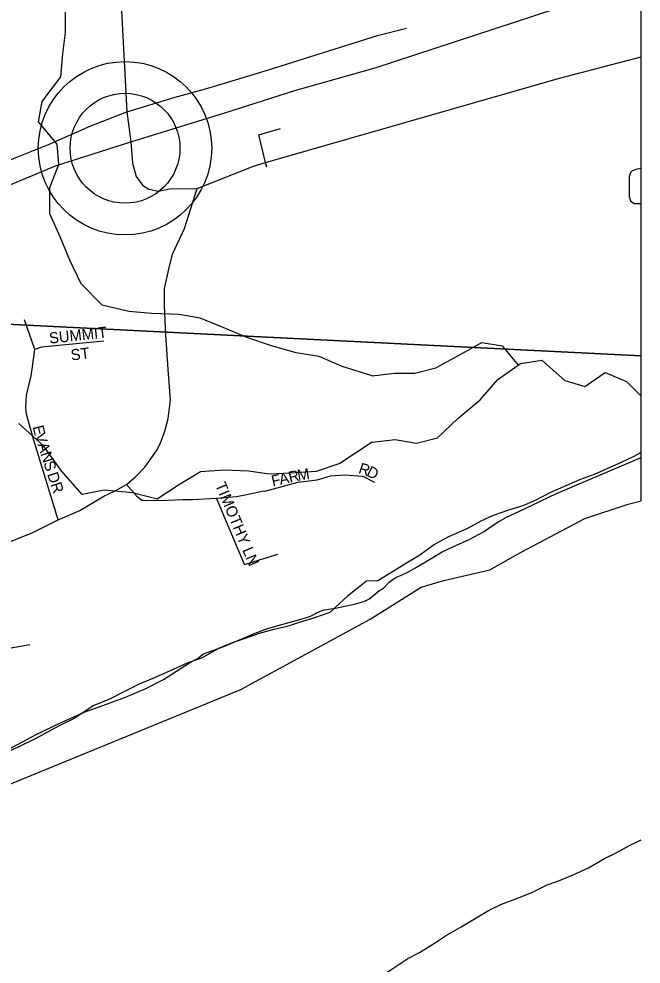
# Model space of a CAD drawing. Extents: x 1949938.81 to 1949945.61, y 152207.65 to 152214.09.
# Drawn here: x 1949945.073 to 1949945.607, y 152208.429 to 152209.24 of the extents above; entities that cross this region are included whole.
import ezdxf

# ---------------------------------------------------------------- set-up
doc = ezdxf.new("R2010")
doc.units = 0
for name, color, linetype in [('GM_X_Airport_Class_3', 7, 'Continuous'), ('GM_X_County', 7, 'Continuous'), ('GM_X_County_Road', 7, 'Continuous'), ('GM_X_Major_River', 7, 'Continuous'), ('GM_X_Minor_River', 7, 'Continuous'), ('GM_X_Section', 7, 'Continuous'), ('GM_X_Township', 7, 'Continuous'), ('GM_X_Township_ROW', 7, 'Continuous'), ('GM_X_Township_Subdivision', 7, 'Continuous'), ('GM_X_Township_Subdivision_Text', 7, 'Continuous'), ('GM_X_Unincorporated', 7, 'Continuous'), ('GM_X_Unincorporated_Location', 7, 'Continuous'), ('GM_X_US_Route', 7, 'Continuous')]:
    doc.layers.add(name, color=color, linetype=linetype)

msp = doc.modelspace()

# ---------------------------------------------------------------- linework, layer by layer
at = {"layer": 'GM_X_Airport_Class_3'}
msp.add_line((1949945.60686, 152209.0816), (1949945.60686, 152209.11163), dxfattribs=at)
msp.add_lwpolyline([(1949945.60686, 152209.11163), (1949945.6022, 152209.11103), (1949945.59893, 152209.10959), (1949945.59774, 152209.10824), (1949945.59671, 152209.10482), (1949945.59667, 152209.08762), (1949945.59786, 152209.08393), (1949945.60099, 152209.08163), (1949945.60686, 152209.0816)], dxfattribs=at)
at = {"layer": 'GM_X_County'}
for points in [[(1949945.60686, 152208.82659), (1949945.60686, 152214.0874), (1949938.80686, 152214.0874), (1949938.80686, 152213.18128)], [(1949942.51034, 152208.01072), (1949942.8268, 152208.00464), (1949942.9926, 152208.00728), (1949943.04181, 152208.01904), (1949943.19019, 152208.0433), (1949943.32418, 152208.05808), (1949943.55507, 152208.10092), (1949944.00133, 152208.20671), (1949944.06493, 152208.23174), (1949944.52367, 152208.38458), (1949944.91164, 152208.52796), (1949945.03125, 152208.56968), (1949945.26327, 152208.66452), (1949945.37438, 152208.72503), (1949945.41796, 152208.75242), (1949945.43768, 152208.75815), (1949945.47712, 152208.76732), (1949945.50403, 152208.78255), (1949945.55862, 152208.81147), (1949945.59578, 152208.82368), (1949945.60686, 152208.82659)]]:
    msp.add_lwpolyline(points, dxfattribs=at)
at = {"layer": 'GM_X_County_Road'}
for points in [[(1949945.16079, 152209.24715), (1949945.16547, 152209.16044), (1949945.16887, 152209.13464)], [(1949945.22775, 152209.17881), (1949945.23695, 152209.18138), (1949945.28721, 152209.19655), (1949945.3807, 152209.22584), (1949945.40543, 152209.23219)], [(1949945.22586, 152209.09445), (1949945.27406, 152209.11376), (1949945.28463, 152209.1168), (1949945.53684, 152209.18937), (1949945.60686, 152209.20755)], [(1949945.16547, 152209.16044), (1949945.20692, 152209.17299), (1949945.22775, 152209.17881)], [(1949944.7487, 152208.97684), (1949944.78583, 152208.98937), (1949944.8436, 152209.01822), (1949944.91631, 152209.05182), (1949944.97891, 152209.07991), (1949944.99822, 152209.09001), (1949945.04072, 152209.1094), (1949945.09823, 152209.13241), (1949945.1345, 152209.14834), (1949945.16547, 152209.16044)], [(1949945.16887, 152209.13464), (1949945.16887, 152209.13464), (1949945.17041, 152209.11644), (1949945.17338, 152209.1048), (1949945.17905, 152209.0975), (1949945.18447, 152209.09397), (1949945.19258, 152209.09235), (1949945.20205, 152209.09425), (1949945.22586, 152209.09445)], [(1949945.08816, 152208.80113), (1949945.10645, 152208.81028), (1949945.12509, 152208.81813), (1949945.14569, 152208.83064), (1949945.1555, 152208.83506), (1949945.16532, 152208.84046), (1949945.17317, 152208.84757), (1949945.18102, 152208.85542), (1949945.19083, 152208.86941), (1949945.19402, 152208.87554), (1949945.19819, 152208.88634), (1949945.20087, 152208.89711), (1949945.20292, 152208.91315), (1949945.20109, 152208.93913), (1949945.19892, 152208.96917), (1949945.1977, 152208.99372), (1949945.19794, 152209.00887), (1949945.2015, 152209.02539), (1949945.20474, 152209.03835), (1949945.2151, 152209.06038), (1949945.22586, 152209.09445)], [(1949944.41994, 152208.55828), (1949944.44868, 152208.57015), (1949944.49406, 152208.58988), (1949944.52449, 152208.60195), (1949944.57656, 152208.61961), (1949944.63875, 152208.63945), (1949944.64745, 152208.64222), (1949944.69231, 152208.65199), (1949944.74952, 152208.67284), (1949944.8104, 152208.69434), (1949944.85513, 152208.70878), (1949944.86482, 152208.7105), (1949944.89699, 152208.72448), (1949944.94572, 152208.7428), (1949944.98591, 152208.76004), (1949945.041, 152208.78201), (1949945.08486, 152208.79948), (1949945.08816, 152208.80113)]]:
    msp.add_lwpolyline(points, dxfattribs=at)
at = {"layer": 'GM_X_Major_River'}
for points in [[(1949945.60686, 152208.86793), (1949945.60018, 152208.86435), (1949945.59036, 152208.85977), (1949945.56654, 152208.84909), (1949945.55406, 152208.84451), (1949945.54234, 152208.83955), (1949945.52911, 152208.83383), (1949945.51588, 152208.82696), (1949945.50529, 152208.82239), (1949945.49395, 152208.81894), (1949945.47996, 152208.81398), (1949945.46937, 152208.80902), (1949945.45728, 152208.80254), (1949945.44102, 152208.7953), (1949945.42968, 152208.7892), (1949945.41608, 152208.7793), (1949945.40626, 152208.77359), (1949945.39492, 152208.76636), (1949945.38094, 152208.75798), (1949945.3711, 152208.75757)], [(1949945.3711, 152208.75757), (1949945.35475, 152208.74461), (1949945.34791, 152208.73854), (1949945.33971, 152208.73064), (1949945.32648, 152208.72609), (1949945.31627, 152208.72306), (1949945.30189, 152208.71851), (1949945.29055, 152208.71586), (1949945.2792, 152208.71283), (1949945.2671, 152208.70828), (1949945.25689, 152208.70487), (1949945.24517, 152208.70032), (1949945.22966, 152208.6916), (1949945.21794, 152208.68743), (1949945.20205, 152208.68023), (1949945.18768, 152208.67416), (1949945.17596, 152208.66924), (1949945.16348, 152208.66279), (1949945.15062, 152208.65635), (1949945.13663, 152208.65066), (1949945.12074, 152208.64005), (1949945.1075, 152208.6336), (1949945.08784, 152208.62299), (1949945.07346, 152208.61579), (1949945.05758, 152208.60859)], [(1949945.37365, 152208.41241), (1949945.3913, 152208.42363), (1949945.40679, 152208.43391), (1949945.41662, 152208.43886), (1949945.42871, 152208.44647), (1949945.43891, 152208.45332), (1949945.45252, 152208.46094), (1949945.46537, 152208.46856), (1949945.47594, 152208.47503), (1949945.48691, 152208.48037), (1949945.49939, 152208.48495), (1949945.513, 152208.49029), (1949945.52623, 152208.49715), (1949945.53682, 152208.50059), (1949945.54854, 152208.50555), (1949945.56177, 152208.51165), (1949945.57537, 152208.51965), (1949945.58558, 152208.52461), (1949945.59692, 152208.5307), (1949945.60686, 152208.53555)]]:
    msp.add_lwpolyline(points, dxfattribs=at)
at = {"layer": 'GM_X_Minor_River'}
for points in [[(1949945.37606, 152208.93377), (1949945.35022, 152208.94196), (1949945.33057, 152208.95038), (1949945.31089, 152208.9535), (1949945.28971, 152208.95965), (1949945.26929, 152208.96656), (1949945.24661, 152208.97575), (1949945.22846, 152208.98342), (1949945.2103, 152208.98652), (1949945.18683, 152208.98737), (1949945.16714, 152208.98896), (1949945.14444, 152208.99436), (1949945.12634, 152209.01265), (1949945.11658, 152209.03319), (1949945.10834, 152209.05297), (1949945.09933, 152209.07274), (1949945.09942, 152209.09552), (1949945.10708, 152209.11524), (1949945.10564, 152209.13272), (1949945.08981, 152209.15176), (1949945.09291, 152209.16922), (1949945.10891, 152209.19042), (1949945.1105, 152209.21017), (1949945.11285, 152209.22839), (1949945.11292, 152209.24586)], [(1949945.37606, 152208.93377), (1949945.39522, 152208.93603), (1949945.41263, 152208.93602), (1949945.4308, 152208.94056), (1949945.45277, 152208.95268), (1949945.4702, 152208.96254), (1949945.48761, 152208.95949), (1949945.50149, 152208.94292)], [(1949945.37605, 152208.87686), (1949945.39589, 152208.87913), (1949945.41405, 152208.87608), (1949945.43222, 152208.88062), (1949945.44966, 152208.8973), (1949945.46861, 152208.91322), (1949945.48378, 152208.93066), (1949945.50348, 152208.9443), (1949945.52165, 152208.94732), (1949945.54131, 152208.92986), (1949945.55871, 152208.92453), (1949945.57614, 152208.93666), (1949945.5943, 152208.92906), (1949945.60686, 152208.91644)], [(1949945.37605, 152208.87686), (1949945.34836, 152208.85845), (1949945.32788, 152208.85169), (1949945.30591, 152208.85025), (1949945.28773, 152208.84956), (1949945.27033, 152208.8519), (1949945.24912, 152208.85274), (1949945.22867, 152208.8513), (1949945.20969, 152208.83998), (1949945.19146, 152208.8279), (1949945.17028, 152208.83329), (1949945.14605, 152208.83566), (1949945.1271, 152208.83194), (1949945.10901, 152208.8525), (1949945.09396, 152208.87382), (1949945.07283, 152208.89288)]]:
    msp.add_lwpolyline(points, dxfattribs=at)
at = {"layer": 'GM_X_Section'}
for p, q in [((1949945.60686, 152208.95108), (1949945.60686, 152209.95427)), ((1949945.60686, 152208.86374), (1949945.60686, 152208.95108))]:
    msp.add_line(p, q, dxfattribs=at)
for points in [[(1949945.60686, 152209.95427), (1949944.65667, 152210.00648), (1949944.60372, 152209.00094), (1949945.60686, 152208.95108)], [(1949945.60686, 152208.95108), (1949944.60372, 152209.00094)], [(1949945.05586, 152208.60925), (1949945.08769, 152208.6259), (1949945.10854, 152208.63612), (1949945.12901, 152208.6452), (1949945.14492, 152208.65087), (1949945.16425, 152208.65805), (1949945.18131, 152208.66524), (1949945.19685, 152208.67319), (1949945.21921, 152208.68758), (1949945.22603, 152208.69136), (1949945.23134, 152208.69514), (1949945.24877, 152208.70157), (1949945.27569, 152208.71292), (1949945.2863, 152208.71708), (1949945.31585, 152208.7254), (1949945.32305, 152208.72767), (1949945.33139, 152208.73183), (1949945.3348, 152208.73296), (1949945.34466, 152208.73447), (1949945.36057, 152208.73787), (1949945.36891, 152208.74014), (1949945.37308, 152208.74203), (1949945.38089, 152208.74835), (1949945.38104, 152208.74847), (1949945.38104, 152208.74878), (1949945.38581, 152208.75173), (1949945.39073, 152208.75666), (1949945.39414, 152208.75931), (1949945.39755, 152208.76121), (1949945.40172, 152208.76311), (1949945.40664, 152208.76538), (1949945.4127, 152208.7688), (1949945.42671, 152208.77715), (1949945.43618, 152208.78283), (1949945.44528, 152208.78701), (1949945.45929, 152208.79346), (1949945.47216, 152208.80029), (1949945.47822, 152208.80446), (1949945.48391, 152208.80825), (1949945.49148, 152208.81243), (1949945.50133, 152208.81698), (1949945.53428, 152208.83292), (1949945.57254, 152208.84924), (1949945.58996, 152208.85645), (1949945.60686, 152208.86374)]]:
    msp.add_lwpolyline(points, dxfattribs=at)
at = {"layer": 'GM_X_Township'}
for points in [[(1949945.60686, 152208.82659), (1949945.60686, 152214.0874), (1949942.68389, 152214.0874)], [(1949942.51034, 152208.01072), (1949942.8268, 152208.00464), (1949942.9926, 152208.00728), (1949943.04181, 152208.01904), (1949943.19019, 152208.0433), (1949943.32418, 152208.05808), (1949943.55507, 152208.10092), (1949944.00133, 152208.20671), (1949944.06493, 152208.23174), (1949944.52367, 152208.38458), (1949944.91164, 152208.52796), (1949945.03125, 152208.56968), (1949945.26327, 152208.66452), (1949945.37438, 152208.72503), (1949945.41796, 152208.75242), (1949945.43768, 152208.75815), (1949945.47712, 152208.76732), (1949945.50403, 152208.78255), (1949945.55862, 152208.81147), (1949945.59578, 152208.82368), (1949945.60686, 152208.82659)]]:
    msp.add_lwpolyline(points, dxfattribs=at)
at = {"layer": 'GM_X_Township_ROW'}
msp.add_lwpolyline([(1949945.08659, 152208.95632), (1949945.0777, 152208.98174)], dxfattribs=at)
at = {"layer": 'GM_X_Township_Subdivision'}
for points in [[(1949945.27864, 152209.14053), (1949945.29743, 152209.146)], [(1949945.28562, 152209.11286), (1949945.28463, 152209.1168), (1949945.27864, 152209.14053)], [(1949945.10645, 152208.81028), (1949945.08545, 152208.87941), (1949945.07941, 152208.90088), (1949945.0787, 152208.90649), (1949945.07941, 152208.91718), (1949945.08169, 152208.92664), (1949945.08344, 152208.93383), (1949945.08466, 152208.94154), (1949945.08659, 152208.95632)], [(1949945.14579, 152208.96348), (1949945.10699, 152208.95974), (1949945.0923, 152208.95845), (1949945.08659, 152208.95632)], [(1949945.26706, 152208.83179), (1949945.28307, 152208.83525), (1949945.28403, 152208.8349), (1949945.31261, 152208.84245), (1949945.32881, 152208.84466), (1949945.34047, 152208.84809), (1949945.35242, 152208.84886), (1949945.36816, 152208.84779), (1949945.378, 152208.84264)], [(1949945.16532, 152208.84046), (1949945.1737, 152208.83098), (1949945.1785, 152208.82724), (1949945.17993, 152208.82704)], [(1949945.17993, 152208.82704), (1949945.18224, 152208.82671), (1949945.20038, 152208.82724), (1949945.21352, 152208.82756)], [(1949945.21352, 152208.82756), (1949945.22225, 152208.82777), (1949945.24238, 152208.82871), (1949945.2596, 152208.83018), (1949945.26706, 152208.83179)], [(1949945.26653, 152208.77204), (1949945.24238, 152208.82871)], [(1949945.26653, 152208.77204), (1949945.29507, 152208.78072)], [(1949945.06142, 152208.69965), (1949945.08226, 152208.70332)]]:
    msp.add_lwpolyline(points, dxfattribs=at)
at = {"layer": 'GM_X_Unincorporated'}
for radius in [0.0744, 0.04716]:
    msp.add_circle((1949945.16393, 152209.12912), radius, dxfattribs=at)
at = {"layer": 'GM_X_Unincorporated_Location'}
msp.add_line((1949945.16393, 152209.12912), (1949945.16393, 152209.12912), dxfattribs=at)
at = {"layer": 'GM_X_US_Route'}
msp.add_lwpolyline([(1949944.70565, 152208.93105), (1949944.75061, 152208.95264), (1949944.86523, 152209.00809), (1949944.96279, 152209.05596), (1949945.03968, 152209.08715), (1949945.1044, 152209.114), (1949945.16887, 152209.13464), (1949945.24969, 152209.15953), (1949945.30962, 152209.17864), (1949945.37874, 152209.19813), (1949945.56792, 152209.26041), (1949945.60686, 152209.27505)], dxfattribs=at)

# ---------------------------------------------------------------- texts
at = {"layer": 'GM_X_Township_Subdivision_Text'}
for s, rotation, p in [('SUMMIT', 6.11557, (1949945.09926, 152208.96141)), ('ST', 7.12418, (1949945.11792, 152208.94691)), ('E', 284.187, (1949945.08452, 152208.89006)), ('V', 286.36927, (1949945.08625, 152208.88322)), ('A', 287.85921, (1949945.08868, 152208.87497)), ('N', 287.91302, (1949945.09124, 152208.86703)), ('S', 287.92043, (1949945.09381, 152208.8591)), ('R', 341.97823, (1949945.36366, 152208.85051)), ('DR', 288.43644, (1949945.09698, 152208.84937)), ('R', 12.6786, (1949945.30536, 152208.84206)), ('M', 9.32832, (1949945.31254, 152208.84368)), ('D', 334.46147, (1949945.37049, 152208.84831)), ('TIMOTHY LN', 292.66955, (1949945.2411, 152208.84032)), ('F', 12.72769, (1949945.29073, 152208.83876)), ('A', 12.73342, (1949945.29724, 152208.84022))]:
    msp.add_text(s, height=0.00947, rotation=rotation, dxfattribs=at).set_placement(p)

doc.saveas('drawing.dxf')
